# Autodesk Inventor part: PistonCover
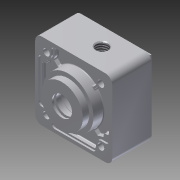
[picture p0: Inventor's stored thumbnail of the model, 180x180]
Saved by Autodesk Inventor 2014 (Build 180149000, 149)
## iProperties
Shininess: 64.0
Length Units: 11269
Angle Units: 11279
Time Units: 11290
Mass Units: 11283
Length Display Precision: 3
Angle Display Precision: 2
Compacted: True
Part Number: PistonCover
Document SubType Name: Modeling
Created: 2002-12
Designer: dayb
Density: 1 g/cm^3
Mass: 49.1989 g
Surface Area: 130.014 cm^2
Volume: 49.1989 cm^3
Material: Generic
Appearance: Default
Density: 0.0
Volumn: 0.0
Area: 0.0
PropertySet Name: Model Information
Control State: 0
Master: False
Checked Out: False
Author: dayb
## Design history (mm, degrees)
sketch "Sketch2"
  geometry: L1 (0, -32.2)-(0, 32.2) reference; L2 (-23, 23)-(23, 23); L3 (23, 23)-(23, -23); L4 (23, -23)-(-23, -23); L5 (-23, -23)-(-23, 23); L6 (-32.2, 0)-(32.2, 0) reference
  constraints: 8 end point, 2 parallel, 1 horizontal, 1 perpendicular
  dimensions: "d4" = 46 distance of L2.start L2.end; "d5" = 46 distance of L2.end L3.end (= d4); "d6" = 23 distance between parallel lines of L1 L3 (= 0.5 x d4); "d7" = 23 distance between parallel lines of L6 L2 (= 0.5 x d5)
extrude "Extrusion2" new body sketch "Sketch2" distance "d8" = 26.5; taper "d9" = 0 deg
sketch "Sketch5"
  geometry: L1 (0, 7.5)-(0, 15); L2 (0, 15)-(-3.2, 15); L3 (-3.2, 15)-(-3.2, 12.5); L4 (-3.2, 12.5)-(-7, 12.5); L5 (-7, 12.5)-(-7, 6); L6 (0, -23)-(0, 23) reference; L7 (-36.389, 0)-(6.065, 0) reference; L8 (0, 0)-(-30.324, 0); L9 (-6, 6)-(-6, 7.5); L10 (-6, 7.5)-(-4.5, 7.5); L11 (-4.5, 7.5)-(-4.5, 6); L12 (0, 7.5)-(-1.5, 7.5); L13 (-1.5, 7.5)-(-1.5, 6); L14 (-7, 6)-(-6, 6); L15 (-4.5, 6)-(-1.5, 6)
  constraints: 26 end point, 10 perpendicular, 3 point on line, 2 collinear, 2 parallel, 1 midpoint
  dimensions: "d11" = 7 distance between parallel lines of L6 L5; "d12" = 3.2 distance between parallel lines of L3 L6; "d15" = 30 diameter of L2 L8; "d16" = 25 diameter of L4 L8; "d71" = 12 diameter of L5.end L8; "d72" = 15 diameter of L10 L8; "d73" = 1.5 distance of L9.end L10.end (= d74); "d74" = 1.5 distance of L1.start L12.end; "d75" = 1 distance of L5.end L9.start
revolve "Revolution1" sketch "Sketch5" stored, may be unused: angle "d17" = 90 deg
sketch "Sketch6"
  geometry: L1 (0, 32.2)-(0, -32.2) reference; L2 (-32.2, 0)-(32.2, 0) reference; 1 further point
  dimensions: "d20" = 32.5 diameter of point (16.25, 16.25) L1; "d21" = 32.5 diameter of point (16.25, 16.25) L2 (= d20)
hole "Hole1" sketch "Sketch6" at (16.25, 16.25) diameter "d22" = 3; stored, may be unused: countersink angle "d26" = 82 deg, drill point angle "d28" = 118 deg; dims "d23" = 6, "d24" = 4, "d25" = 4, "d27" = 8
mirror "Mirror1"
mirror "Mirror2"
fillet "Fillet1" dims "d29" = 4
sketch "Sketch7"
  geometry: L1 (23, -19)-(23, 19) reference; L2 (19, 23)-(-19, 23) reference; L3 (-19, -23)-(19, -23) reference; L4 (13.25, 16.25)-(13.25, 21); L5 (13.25, 21)-(0, 21); L6 (16.25, 13.25)-(21, 13.25); L7 (0, 32.2)-(0, -32.2) reference; L8 (-32.2, 0)-(32.2, 0) reference; L9 (21, 13.25)-(21, 0); L10 (0, 21)-(0, 15); L11 (21, 0)-(15, 0); C1 r 2 at (16.25, 16.25) reference; A1 r 3 centre (16.25, 16.25) between (13.25, 16.25) and (16.25, 13.25); A2 r 15 centre (0, 0) between (15, 0) and (0, 15); 1 further point
  constraints: 12 end point, 4 point on circle, 3 perpendicular, 2 centre point, 2 coincident, 2 collinear, 2 point on line, 2 tangent, 1 concentric, 1 parallel, 1 vertical alignment, 1 other
  dimensions: "d30" = 6 diameter of A1; "d31" = 2 distance between parallel lines of L2 L5 (= d32); "d32" = 2 distance between parallel lines of L1 L9
extrude "Extrusion3" cut sketch "Sketch7" distance "d33" = 1; taper "d34" = 0 deg
fillet "Fillet3" dims "d36" = 2
mirror "Mirror3"
mirror "Mirror4"
sketch "Sketch10"
  geometry: L1 (21, 11.25)-(21, -11.25) reference; L2 (19, 13.25)-(16.25, 13.25) reference; L3 (-13.25, 16.25)-(-13.25, 19) reference; L4 (0, 0)-(16.25, 16.25); L5 (13.797, 13.09)-(10.954, 10.247); L6 (16.25, 12.25)-(19, 12.25); L7 (20, 11.25)-(20, 0); L8 (20, 0)-(15, 0); A1 r 15 centre (0, 0) between (10.954, 10.247) and (15, 0) reference; A2 r 2 centre (19, 11.25) between (21, 11.25) and (19, 13.25) reference; A3 r 3 centre (16.25, 16.25) between (13.25, 16.25) and (16.25, 13.25) reference; A4 r 3 centre (-16.25, 16.25) between (-16.25, 13.25) and (-13.25, 16.25) reference; A5 r 4.134 centre (-16.25, 16.25) between (-13.406, 13.25) and (-13.25, 13.406); A6 r 4 centre (16.25, 16.25) between (13.797, 13.09) and (16.25, 12.25); A7 r 1 centre (19, 11.25) between (20, 11.25) and (19, 12.25)
  constraints: 10 end point, 8 point on circle, 3 centre point, 2 point on line, 1 parallel, 1 perpendicular, 1 other
  dimensions: "d44" = 0.5 distance between parallel lines of L4 L5; "d45" = 1 distance between parallel lines of L1 L7
extrude "Extrusion4" cut sketch "Sketch10" distance "d46" = 2; taper "d47" = 0 deg
sketch "Sketch11"
  geometry: L1 (11.25, 21)-(-11.25, 21) reference; L2 (10.954, 10.247)-(13.797, 13.09) reference; L3 (0, 0)-(16.25, 16.25); L4 (12.78, 13.487)-(10.247, 10.954); L5 (0, 20)-(9.269, 20); L6 (0, 20)-(0, 15); L7 (20, 0)-(15, 0) reference; L8 (9.269, 20)-(9.269, 18); L9 (10.269, 17)-(11.878, 17); A1 r 3 centre (16.25, 16.25) between (13.25, 16.25) and (16.25, 13.25) reference; A2 r 4 centre (16.25, 16.25) between (13.797, 13.09) and (16.25, 12.25) reference; A3 r 15 centre (0, 0) between (10.954, 10.247) and (15, 0) reference; A4 r 4.436 centre (16.25, 16.25) between (11.878, 17) and (12.78, 13.487); A5 r 1 centre (10.269, 18) between (9.269, 18) and (10.269, 17); 6 further points
  constraints: 12 end point, 6 point on circle, 2 centre point, 2 parallel, 2 perpendicular, 2 tangent
  dimensions: "d48" = 1 distance between parallel lines of L5 L1 (= d45); "d49" = 0.5 distance between parallel lines of L3 L4 (= d44); "d52" = 1 radius of A5; "d53" = 4 distance between parallel lines of L1 L9
extrude "Extrusion5" cut sketch "Sketch11" distance "d50" = 2; taper "d51" = 0 deg
pattern_circular "Circular Pattern1" dims angle "d58" = 360 deg
fillet "Fillet5" dims "d59" = 0.5, "d60" = 1
sketch "Sketch12"
  geometry: L1 (-6, -6)-(-6, -7) reference; L2 (6, -6)-(6, -7) reference; L3 (0, 33.2)-(0, -13.7) reference; L4 (19, 26.5)-(-19, 26.5) reference; L5 (0, 26.5)-(0, 0); L6 (0, 26.5)-(0, 0); L7 (7.345, 26.5)-(7.345, 0); 3 further points
  constraints: 6 end point, 3 point on line, 1 midpoint, 1 vertical, 3 other
revolve "Revolution2" sketch "Sketch12" stored, may be unused: angle "d61" = 90 deg
sketch "Sketch14"
  geometry: L1 (26.5, 23)-(0, 23) reference; L2 (26.5, 23)-(26.5, 19) reference; L3 (26.5, 23)-(23.5, 23); L4 (23.5, 23)-(23.5, 20); L5 (26.5, 20)-(26.5, 23); L6 (23.5, 20)-(24.25, 20); L7 (25.75, 20)-(26.5, 20); A1 r 0.75 centre (25, 20) between (24.25, 20) and (25.75, 20)
  constraints: 10 end point, 3 parallel, 2 point on circle, 1 centre point, 1 horizontal, 1 perpendicular
  dimensions: "d62" = 3 distance of L1.start L3.end; "d63" = 3 distance of L3.end L4.end (= d62); "d64" = 1.5 diameter of A1; "d65" = 1.5 distance from line of L2 A1.centre (= 0.5 x d63)
extrude "Extrusion6" cut sketch "Sketch14" stored distance "d66" = 2; taper "d67" = 0 deg
pattern_circular "Circular Pattern2" dims angle "d70" = 360 deg
workplane "Work Plane1"
sketch "Sketch16"
  geometry: L1 (23.5, 23)-(0, 23) reference; L2 (0, -23)-(23.5, -23) reference; L3 (13, 23)-(13, -23); L4 (0, -19)-(0, 19) reference; L5 (13, 23)-(16.5, 23); L6 (0, 7.345)-(26.5, 7.345) reference; L7 (16.5, 23)-(16.5, 0); L8 (13, 23)-(13, 0); L9 (16.5, 0)-(13, 0); L10 (-5.3, 0)-(31.8, 0) reference
  constraints: 10 end point, 3 perpendicular, 3 point on line, 1 collinear, 1 midpoint
  dimensions: "d80" = 13 distance between parallel lines of L4 L3; "d81" = 7 diameter of L7 L3
revolve "Revolution3" sketch "Sketch16" stored, may be unused: angle "d82" = 90 deg
chamfer "Chamfer1" distance "d83" = 0.5; stored, may be unused: second distance "d84" = 2, angle "d91" = 45 deg
thread "Thread1" dims "d85" = 10, "d86" = 0
body "Solid1"
other parameters: "d13" = 12, "d38" = 8, "d76" = 4
